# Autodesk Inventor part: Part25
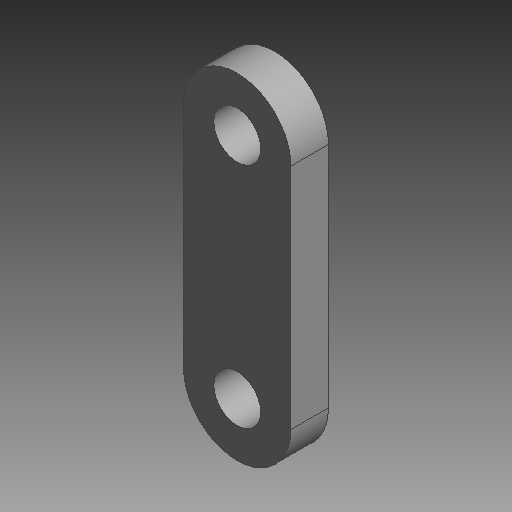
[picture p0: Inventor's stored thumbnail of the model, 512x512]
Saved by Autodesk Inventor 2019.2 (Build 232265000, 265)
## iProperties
Part Number: Part25
Material: Generic
Document SubType Name: Modeling
Designer: richard.girt
Mass: 0.467665 g
Surface Area: 5.61193 cm^2
Volume: 0.467665 cm^3
Density: 1 g/cm^3
Appearance: Default
Author: richard.girt
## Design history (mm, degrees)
sketch "Sketch1"
  geometry: L1 (0, 0)-(0, 17); L2 (4, 0)-(4, 17); L3 (-4, 17)-(-4, 0); C1 r 4 at (0, 0); A1 r 4 centre (0, 0) between (-4, 0) and (4, 0); A2 r 4 centre (0, 17) between (4, 17) and (-4, 17); 2 further points
  constraints: 8 end point, 5 tangent, 4 point on circle, 3 centre point, 2 coincident, 1 midpoint, 1 parallel, 1 vertical
  dimensions: "d0" = 8 diameter of C1; "d1" = 8 distance between parallel lines of L2 L3; "d2" = 17 distance of point (0, 0) L1.end
extrude "Extrusion1" new body sketch "Sketch1" stored distance "d3" = 2.8; taper "d4" = 0 deg
sketch "Sketch2"
  geometry: L1 (0, 12.7)-(0, 5.7); L2 (-1.3, 11.4)-(-1.3, 7); L3 (1.3, 7)-(1.3, 11.4); C1 r 1.75 at (0, 0); C2 r 1.75 at (0, 17); A1 r 4 centre (0, 17) between (4, 17) and (-4, 17) reference; A2 r 4 centre (0, 0) between (-4, 0) and (4, 0) reference; A3 r 1.3 centre (0, 11.4) between (1.3, 11.4) and (-1.3, 11.4); A4 r 1.3 centre (0, 7) between (-1.3, 7) and (1.3, 7); 1 further point
  constraints: 8 end point, 6 point on circle, 4 centre point, 4 tangent, 2 coincident, 2 point on line, 1 midpoint, 1 parallel, 1 vertical, 1 vertical alignment
  dimensions: "d5" = 7 distance of L1.start L1.end; "d6" = 2.6 distance between parallel lines of L2 L3; "d7" = 7 distance of A4.centre C1.centre; "d8" = 3.5 diameter of C2; "d9" = 3.5 diameter of C1
extrude "Extrusion2" cut sketch "Sketch2" extent not by distance; stored distance "d10" = 2.8; taper "d11" = 0 deg
body "Solid1"
